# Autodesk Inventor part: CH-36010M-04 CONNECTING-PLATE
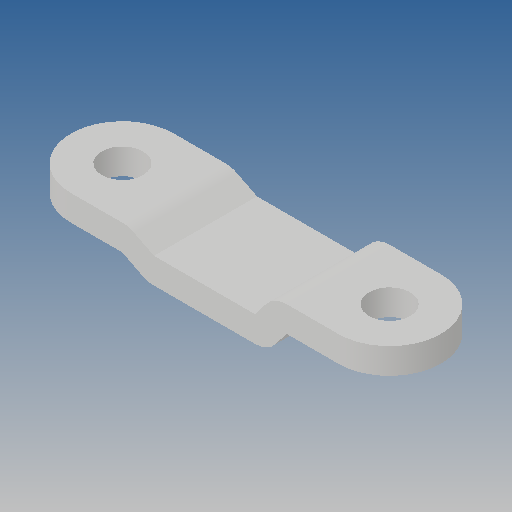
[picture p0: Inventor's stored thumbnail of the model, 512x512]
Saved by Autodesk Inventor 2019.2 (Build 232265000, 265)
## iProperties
Created: 2012-09
Part Number: CH-36010M-04 CONNECTING-PLATE
Material: Ogólny
Document SubType Name: Modeling
Designer: CADENGINEERING4
Density: 1 g/cm^3
Appearance: Domyślna
Author: CADENGINEERING4
Revision Number: ÈÎºÎ
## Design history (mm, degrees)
feature "ÇÐ³ý-À­Éì1"
node "Bryła1"
